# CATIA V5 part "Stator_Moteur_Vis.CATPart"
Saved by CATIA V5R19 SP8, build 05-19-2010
Part number: Stator_Moteur_Vis
Nomenclature: 70_d
Bounding box of the stored display mesh (mm): x -30.4 to 32.4, y -32.4 to 32.4, z -30 to 0
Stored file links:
  C:\Users\rphgr\Desktop\0_Tapis_TC520B_vitesse\Stator_Moteur_Vis.CATPart
  D:\Documents\1_Travail\1 - ac-limoges.fr\ac-limoges.fr\Emmanuel Maynard - STI2D_Turgot\3 - Supports\Tapis de course TC520B\Tapis de course TC520B_Ca\CE_Boitier_Moteur_Vis.CATProduct
  D:\Documents\1_Travail\1 - ac-limoges.fr\ac-limoges.fr\Emmanuel Maynard - STI2D_Turgot\3 - Supports\Tapis de course TC520B\Tapis de course TC520B_Ca\Corps Inf de BMV.CATPart
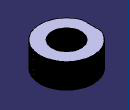
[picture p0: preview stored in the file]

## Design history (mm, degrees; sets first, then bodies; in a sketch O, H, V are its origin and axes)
Set1
  DatumCurve1
  DatumCurve2
Body1 (main body)
  AxisSystem1: origin (0, 0, 0), X (1, 0, 0), Y (0, 1, 0), Z (0, 0, 1)
  Sketch1 on XY plane of AxisSystem1, origin (0, 0, 0), H (1, 0, 0), V (0, 1, 0)
    projected line E2 (-30.4, -11.2101) -> (-30.4, 11.2101) from edge of DatumCurve2
    circle A1 centre (0, 0) radius 17.5
    radius A1 = 17.5
  Pad1: profile Sketch1, direction (0, 0, -1), length 1
  Fillet1: radius 0.1, on end face of Pad1; start face of Pad1
  RectPattern1: of the body so far, direction 1 instances 30, spacing 1, along edge [ZX plane of AxisSystem1 | YZ plane of AxisSystem1] reversed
